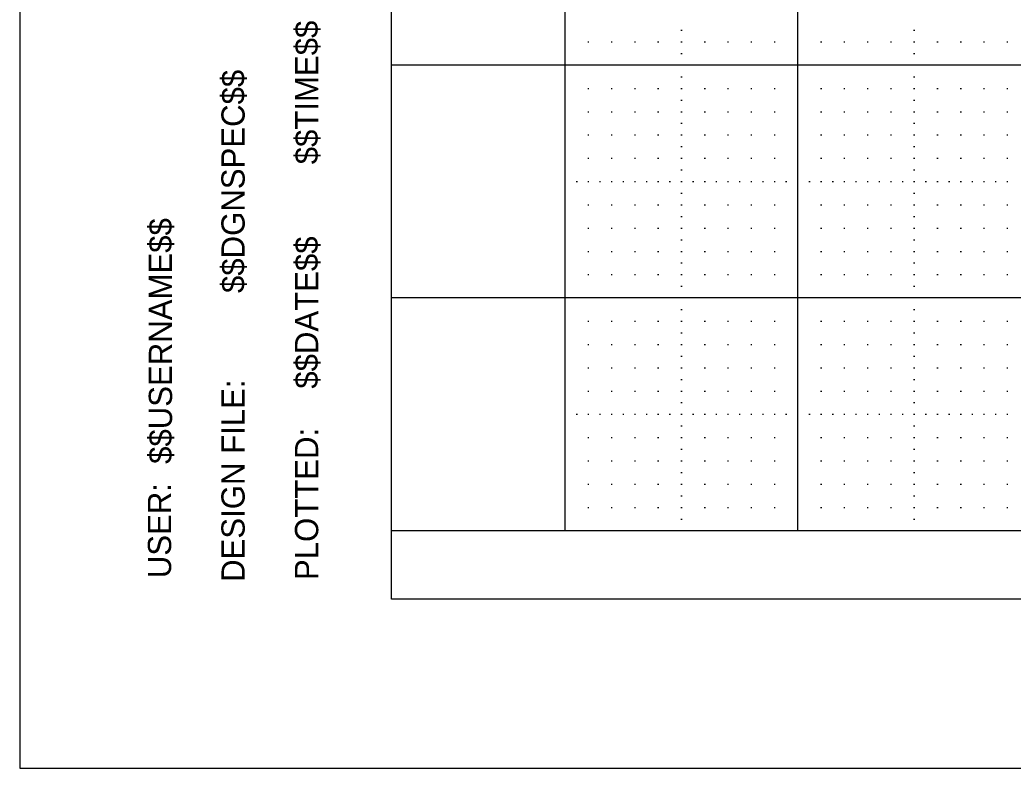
# Model space of a CAD drawing. Extents: x 0 to 34.3, y 0 to 22.
# Drawn here: x 0 to 4.268, y 0 to 3.214 of the extents above; entities that cross this region are included whole.
import ezdxf

# ---------------------------------------------------------------- set-up
doc = ezdxf.new("R2010")
doc.units = 0
for name, color, linetype in [('Level 1', 7, 'Continuous'), ('Level 4', 7, 'Continuous'), ('Level 5', 7, 'Continuous'), ('Level 63', 7, 'Continuous'), ('R_Border_Dark', 7, 'Continuous')]:
    doc.layers.add(name, color=color, linetype=linetype)

msp = doc.modelspace()

# ---------------------------------------------------------------- linework, layer by layer
at = {"layer": 'Level 1'}
for p, q in [((1.597, 0.726), (1.597, 21.272)), ((33.215, 0.726), (1.597, 0.726))]:
    msp.add_line(p, q, dxfattribs=at)
msp.add_lwpolyline([(2.343, 9.02), (32.343, 9.02), (32.343, 1.02), (2.343, 1.02)], close=True, dxfattribs=at)
at = {"layer": 'Level 4'}
msp.add_line((33.215, 1.02), (1.597, 1.02), dxfattribs=at)
at = {"layer": 'Level 5'}
for p, q in [((2.8405, 3.17), (2.8455, 3.17)), ((3.8405, 3.17), (3.8455, 3.17)), ((2.4405, 3.12), (2.4455, 3.12)), ((2.5405, 3.12), (2.5455, 3.12)), ((2.6405, 3.12), (2.6455, 3.12)), ((2.7405, 3.12), (2.7455, 3.12)), ((2.8405, 3.12), (2.8455, 3.12)), ((2.9405, 3.12), (2.9455, 3.12)), ((3.0405, 3.12), (3.0455, 3.12)), ((3.1405, 3.12), (3.1455, 3.12)), ((3.2405, 3.12), (3.2455, 3.12)), ((3.4405, 3.12), (3.4455, 3.12)), ((3.5405, 3.12), (3.5455, 3.12)), ((3.6405, 3.12), (3.6455, 3.12)), ((3.7405, 3.12), (3.7455, 3.12)), ((3.8405, 3.12), (3.8455, 3.12)), ((3.9405, 3.12), (3.9455, 3.12)), ((4.0405, 3.12), (4.0455, 3.12)), ((4.1405, 3.12), (4.1455, 3.12)), ((4.2405, 3.12), (4.2455, 3.12)), ((2.8405, 3.07), (2.8455, 3.07)), ((3.8405, 3.07), (3.8455, 3.07)), ((2.8405, 2.97), (2.8455, 2.97)), ((3.8405, 2.97), (3.8455, 2.97)), ((2.4405, 2.92), (2.4455, 2.92)), ((2.5405, 2.92), (2.5455, 2.92)), ((2.6405, 2.92), (2.6455, 2.92)), ((2.7405, 2.92), (2.7455, 2.92)), ((2.8405, 2.92), (2.8455, 2.92)), ((2.9405, 2.92), (2.9455, 2.92)), ((3.0405, 2.92), (3.0455, 2.92)), ((3.1405, 2.92), (3.1455, 2.92)), ((3.2405, 2.92), (3.2455, 2.92)), ((3.4405, 2.92), (3.4455, 2.92)), ((3.5405, 2.92), (3.5455, 2.92)), ((3.6405, 2.92), (3.6455, 2.92)), ((3.7405, 2.92), (3.7455, 2.92)), ((3.8405, 2.92), (3.8455, 2.92)), ((3.9405, 2.92), (3.9455, 2.92)), ((4.0405, 2.92), (4.0455, 2.92)), ((4.1405, 2.92), (4.1455, 2.92)), ((4.2405, 2.92), (4.2455, 2.92)), ((2.8405, 2.87), (2.8455, 2.87)), ((3.8405, 2.87), (3.8455, 2.87)), ((2.4405, 2.82), (2.4455, 2.82)), ((2.5405, 2.82), (2.5455, 2.82)), ((2.6405, 2.82), (2.6455, 2.82)), ((2.7405, 2.82), (2.7455, 2.82)), ((2.8405, 2.82), (2.8455, 2.82)), ((2.9405, 2.82), (2.9455, 2.82)), ((3.0405, 2.82), (3.0455, 2.82)), ((3.1405, 2.82), (3.1455, 2.82)), ((3.2405, 2.82), (3.2455, 2.82)), ((3.4405, 2.82), (3.4455, 2.82)), ((3.5405, 2.82), (3.5455, 2.82)), ((3.6405, 2.82), (3.6455, 2.82)), ((3.7405, 2.82), (3.7455, 2.82)), ((3.8405, 2.82), (3.8455, 2.82)), ((3.9405, 2.82), (3.9455, 2.82)), ((4.0405, 2.82), (4.0455, 2.82)), ((4.1405, 2.82), (4.1455, 2.82)), ((4.2405, 2.82), (4.2455, 2.82)), ((2.8405, 2.77), (2.8455, 2.77)), ((3.8405, 2.77), (3.8455, 2.77)), ((2.4405, 2.72), (2.4455, 2.72)), ((2.5405, 2.72), (2.5455, 2.72)), ((2.6405, 2.72), (2.6455, 2.72)), ((2.7405, 2.72), (2.7455, 2.72)), ((2.8405, 2.72), (2.8455, 2.72)), ((2.9405, 2.72), (2.9455, 2.72)), ((3.0405, 2.72), (3.0455, 2.72)), ((3.1405, 2.72), (3.1455, 2.72)), ((3.2405, 2.72), (3.2455, 2.72)), ((3.4405, 2.72), (3.4455, 2.72)), ((3.5405, 2.72), (3.5455, 2.72)), ((3.6405, 2.72), (3.6455, 2.72)), ((3.7405, 2.72), (3.7455, 2.72)), ((3.8405, 2.72), (3.8455, 2.72)), ((3.9405, 2.72), (3.9455, 2.72)), ((4.0405, 2.72), (4.0455, 2.72)), ((4.1405, 2.72), (4.1455, 2.72)), ((4.2405, 2.72), (4.2455, 2.72)), ((2.8405, 2.67), (2.8455, 2.67)), ((3.8405, 2.67), (3.8455, 2.67)), ((2.4405, 2.62), (2.4455, 2.62)), ((2.5405, 2.62), (2.5455, 2.62)), ((2.6405, 2.62), (2.6455, 2.62)), ((2.7405, 2.62), (2.7455, 2.62)), ((2.8405, 2.62), (2.8455, 2.62)), ((2.9405, 2.62), (2.9455, 2.62)), ((3.0405, 2.62), (3.0455, 2.62)), ((3.1405, 2.62), (3.1455, 2.62)), ((3.2405, 2.62), (3.2455, 2.62)), ((3.4405, 2.62), (3.4455, 2.62)), ((3.5405, 2.62), (3.5455, 2.62)), ((3.6405, 2.62), (3.6455, 2.62)), ((3.7405, 2.62), (3.7455, 2.62)), ((3.8405, 2.62), (3.8455, 2.62)), ((3.9405, 2.62), (3.9455, 2.62)), ((4.0405, 2.62), (4.0455, 2.62)), ((4.1405, 2.62), (4.1455, 2.62)), ((4.2405, 2.62), (4.2455, 2.62)), ((2.8405, 2.57), (2.8455, 2.57)), ((3.8405, 2.57), (3.8455, 2.57)), ((2.3905, 2.52), (2.3955, 2.52)), ((2.4405, 2.52), (2.4455, 2.52)), ((2.4905, 2.52), (2.4955, 2.52)), ((2.5405, 2.52), (2.5455, 2.52)), ((2.5905, 2.52), (2.5955, 2.52)), ((2.6405, 2.52), (2.6455, 2.52)), ((2.6905, 2.52), (2.6955, 2.52)), ((2.7405, 2.52), (2.7455, 2.52)), ((2.7905, 2.52), (2.7955, 2.52)), ((2.8405, 2.52), (2.8455, 2.52)), ((2.8905, 2.52), (2.8955, 2.52)), ((2.9405, 2.52), (2.9455, 2.52)), ((2.9905, 2.52), (2.9955, 2.52)), ((3.0405, 2.52), (3.0455, 2.52)), ((3.0905, 2.52), (3.0955, 2.52)), ((3.1405, 2.52), (3.1455, 2.52)), ((3.1905, 2.52), (3.1955, 2.52)), ((3.2405, 2.52), (3.2455, 2.52)), ((3.2905, 2.52), (3.2955, 2.52)), ((3.3905, 2.52), (3.3955, 2.52)), ((3.4405, 2.52), (3.4455, 2.52)), ((3.4905, 2.52), (3.4955, 2.52)), ((3.5405, 2.52), (3.5455, 2.52)), ((3.5905, 2.52), (3.5955, 2.52)), ((3.6405, 2.52), (3.6455, 2.52)), ((3.6905, 2.52), (3.6955, 2.52)), ((3.7405, 2.52), (3.7455, 2.52)), ((3.7905, 2.52), (3.7955, 2.52)), ((3.8405, 2.52), (3.8455, 2.52)), ((3.8905, 2.52), (3.8955, 2.52)), ((3.9405, 2.52), (3.9455, 2.52)), ((3.9905, 2.52), (3.9955, 2.52)), ((4.0405, 2.52), (4.0455, 2.52)), ((4.0905, 2.52), (4.0955, 2.52)), ((4.1405, 2.52), (4.1455, 2.52)), ((4.1905, 2.52), (4.1955, 2.52)), ((4.2405, 2.52), (4.2455, 2.52)), ((2.8405, 2.47), (2.8455, 2.47)), ((3.8405, 2.47), (3.8455, 2.47)), ((2.4405, 2.42), (2.4455, 2.42)), ((2.5405, 2.42), (2.5455, 2.42)), ((2.6405, 2.42), (2.6455, 2.42)), ((2.7405, 2.42), (2.7455, 2.42)), ((2.8405, 2.42), (2.8455, 2.42)), ((2.9405, 2.42), (2.9455, 2.42)), ((3.0405, 2.42), (3.0455, 2.42)), ((3.1405, 2.42), (3.1455, 2.42)), ((3.2405, 2.42), (3.2455, 2.42)), ((3.4405, 2.42), (3.4455, 2.42)), ((3.5405, 2.42), (3.5455, 2.42)), ((3.6405, 2.42), (3.6455, 2.42)), ((3.7405, 2.42), (3.7455, 2.42)), ((3.8405, 2.42), (3.8455, 2.42)), ((3.9405, 2.42), (3.9455, 2.42)), ((4.0405, 2.42), (4.0455, 2.42)), ((4.1405, 2.42), (4.1455, 2.42)), ((4.2405, 2.42), (4.2455, 2.42)), ((2.8405, 2.37), (2.8455, 2.37)), ((3.8405, 2.37), (3.8455, 2.37)), ((2.4405, 2.32), (2.4455, 2.32)), ((2.5405, 2.32), (2.5455, 2.32)), ((2.6405, 2.32), (2.6455, 2.32)), ((2.7405, 2.32), (2.7455, 2.32)), ((2.8405, 2.32), (2.8455, 2.32)), ((2.9405, 2.32), (2.9455, 2.32)), ((3.0405, 2.32), (3.0455, 2.32)), ((3.1405, 2.32), (3.1455, 2.32)), ((3.2405, 2.32), (3.2455, 2.32)), ((3.4405, 2.32), (3.4455, 2.32)), ((3.5405, 2.32), (3.5455, 2.32)), ((3.6405, 2.32), (3.6455, 2.32)), ((3.7405, 2.32), (3.7455, 2.32)), ((3.8405, 2.32), (3.8455, 2.32)), ((3.9405, 2.32), (3.9455, 2.32)), ((4.0405, 2.32), (4.0455, 2.32)), ((4.1405, 2.32), (4.1455, 2.32)), ((4.2405, 2.32), (4.2455, 2.32)), ((2.8405, 2.27), (2.8455, 2.27)), ((3.8405, 2.27), (3.8455, 2.27)), ((2.4405, 2.22), (2.4455, 2.22)), ((2.5405, 2.22), (2.5455, 2.22)), ((2.6405, 2.22), (2.6455, 2.22)), ((2.7405, 2.22), (2.7455, 2.22)), ((2.8405, 2.22), (2.8455, 2.22)), ((2.9405, 2.22), (2.9455, 2.22)), ((3.0405, 2.22), (3.0455, 2.22)), ((3.1405, 2.22), (3.1455, 2.22)), ((3.2405, 2.22), (3.2455, 2.22)), ((3.4405, 2.22), (3.4455, 2.22)), ((3.5405, 2.22), (3.5455, 2.22)), ((3.6405, 2.22), (3.6455, 2.22)), ((3.7405, 2.22), (3.7455, 2.22)), ((3.8405, 2.22), (3.8455, 2.22)), ((3.9405, 2.22), (3.9455, 2.22)), ((4.0405, 2.22), (4.0455, 2.22)), ((4.1405, 2.22), (4.1455, 2.22)), ((4.2405, 2.22), (4.2455, 2.22)), ((2.8405, 2.17), (2.8455, 2.17)), ((3.8405, 2.17), (3.8455, 2.17)), ((2.4405, 2.12), (2.4455, 2.12)), ((2.5405, 2.12), (2.5455, 2.12)), ((2.6405, 2.12), (2.6455, 2.12)), ((2.7405, 2.12), (2.7455, 2.12)), ((2.8405, 2.12), (2.8455, 2.12)), ((2.9405, 2.12), (2.9455, 2.12)), ((3.0405, 2.12), (3.0455, 2.12)), ((3.1405, 2.12), (3.1455, 2.12)), ((3.2405, 2.12), (3.2455, 2.12)), ((3.4405, 2.12), (3.4455, 2.12)), ((3.5405, 2.12), (3.5455, 2.12)), ((3.6405, 2.12), (3.6455, 2.12)), ((3.7405, 2.12), (3.7455, 2.12)), ((3.8405, 2.12), (3.8455, 2.12)), ((3.9405, 2.12), (3.9455, 2.12)), ((4.0405, 2.12), (4.0455, 2.12)), ((4.1405, 2.12), (4.1455, 2.12)), ((4.2405, 2.12), (4.2455, 2.12)), ((2.8405, 2.07), (2.8455, 2.07)), ((3.8405, 2.07), (3.8455, 2.07)), ((2.8405, 1.97), (2.8455, 1.97)), ((3.8405, 1.97), (3.8455, 1.97)), ((2.4405, 1.92), (2.4455, 1.92)), ((2.5405, 1.92), (2.5455, 1.92)), ((2.6405, 1.92), (2.6455, 1.92)), ((2.7405, 1.92), (2.7455, 1.92)), ((2.8405, 1.92), (2.8455, 1.92)), ((2.9405, 1.92), (2.9455, 1.92)), ((3.0405, 1.92), (3.0455, 1.92)), ((3.1405, 1.92), (3.1455, 1.92)), ((3.2405, 1.92), (3.2455, 1.92)), ((3.4405, 1.92), (3.4455, 1.92)), ((3.5405, 1.92), (3.5455, 1.92)), ((3.6405, 1.92), (3.6455, 1.92)), ((3.7405, 1.92), (3.7455, 1.92)), ((3.8405, 1.92), (3.8455, 1.92)), ((3.9405, 1.92), (3.9455, 1.92)), ((4.0405, 1.92), (4.0455, 1.92)), ((4.1405, 1.92), (4.1455, 1.92)), ((4.2405, 1.92), (4.2455, 1.92)), ((2.8405, 1.87), (2.8455, 1.87)), ((3.8405, 1.87), (3.8455, 1.87)), ((2.4405, 1.82), (2.4455, 1.82)), ((2.5405, 1.82), (2.5455, 1.82)), ((2.6405, 1.82), (2.6455, 1.82)), ((2.7405, 1.82), (2.7455, 1.82)), ((2.8405, 1.82), (2.8455, 1.82)), ((2.9405, 1.82), (2.9455, 1.82)), ((3.0405, 1.82), (3.0455, 1.82)), ((3.1405, 1.82), (3.1455, 1.82)), ((3.2405, 1.82), (3.2455, 1.82)), ((3.4405, 1.82), (3.4455, 1.82)), ((3.5405, 1.82), (3.5455, 1.82)), ((3.6405, 1.82), (3.6455, 1.82)), ((3.7405, 1.82), (3.7455, 1.82)), ((3.8405, 1.82), (3.8455, 1.82)), ((3.9405, 1.82), (3.9455, 1.82)), ((4.0405, 1.82), (4.0455, 1.82)), ((4.1405, 1.82), (4.1455, 1.82)), ((4.2405, 1.82), (4.2455, 1.82)), ((2.8405, 1.77), (2.8455, 1.77)), ((3.8405, 1.77), (3.8455, 1.77)), ((2.4405, 1.72), (2.4455, 1.72)), ((2.5405, 1.72), (2.5455, 1.72)), ((2.6405, 1.72), (2.6455, 1.72)), ((2.7405, 1.72), (2.7455, 1.72)), ((2.8405, 1.72), (2.8455, 1.72)), ((2.9405, 1.72), (2.9455, 1.72)), ((3.0405, 1.72), (3.0455, 1.72)), ((3.1405, 1.72), (3.1455, 1.72)), ((3.2405, 1.72), (3.2455, 1.72)), ((3.4405, 1.72), (3.4455, 1.72)), ((3.5405, 1.72), (3.5455, 1.72)), ((3.6405, 1.72), (3.6455, 1.72)), ((3.7405, 1.72), (3.7455, 1.72)), ((3.8405, 1.72), (3.8455, 1.72)), ((3.9405, 1.72), (3.9455, 1.72)), ((4.0405, 1.72), (4.0455, 1.72)), ((4.1405, 1.72), (4.1455, 1.72)), ((4.2405, 1.72), (4.2455, 1.72)), ((2.8405, 1.67), (2.8455, 1.67)), ((3.8405, 1.67), (3.8455, 1.67)), ((2.4405, 1.62), (2.4455, 1.62)), ((2.5405, 1.62), (2.5455, 1.62)), ((2.6405, 1.62), (2.6455, 1.62)), ((2.7405, 1.62), (2.7455, 1.62)), ((2.8405, 1.62), (2.8455, 1.62)), ((2.9405, 1.62), (2.9455, 1.62)), ((3.0405, 1.62), (3.0455, 1.62)), ((3.1405, 1.62), (3.1455, 1.62)), ((3.2405, 1.62), (3.2455, 1.62)), ((3.4405, 1.62), (3.4455, 1.62)), ((3.5405, 1.62), (3.5455, 1.62)), ((3.6405, 1.62), (3.6455, 1.62)), ((3.7405, 1.62), (3.7455, 1.62)), ((3.8405, 1.62), (3.8455, 1.62)), ((3.9405, 1.62), (3.9455, 1.62)), ((4.0405, 1.62), (4.0455, 1.62)), ((4.1405, 1.62), (4.1455, 1.62)), ((4.2405, 1.62), (4.2455, 1.62)), ((2.8405, 1.57), (2.8455, 1.57)), ((3.8405, 1.57), (3.8455, 1.57)), ((2.3905, 1.52), (2.3955, 1.52)), ((2.4405, 1.52), (2.4455, 1.52)), ((2.4905, 1.52), (2.4955, 1.52)), ((2.5405, 1.52), (2.5455, 1.52)), ((2.5905, 1.52), (2.5955, 1.52)), ((2.6405, 1.52), (2.6455, 1.52)), ((2.6905, 1.52), (2.6955, 1.52)), ((2.7405, 1.52), (2.7455, 1.52)), ((2.7905, 1.52), (2.7955, 1.52)), ((2.8405, 1.52), (2.8455, 1.52)), ((2.8905, 1.52), (2.8955, 1.52)), ((2.9405, 1.52), (2.9455, 1.52)), ((2.9905, 1.52), (2.9955, 1.52)), ((3.0405, 1.52), (3.0455, 1.52)), ((3.0905, 1.52), (3.0955, 1.52)), ((3.1405, 1.52), (3.1455, 1.52)), ((3.1905, 1.52), (3.1955, 1.52)), ((3.2405, 1.52), (3.2455, 1.52)), ((3.2905, 1.52), (3.2955, 1.52)), ((3.3905, 1.52), (3.3955, 1.52)), ((3.4405, 1.52), (3.4455, 1.52)), ((3.4905, 1.52), (3.4955, 1.52)), ((3.5405, 1.52), (3.5455, 1.52)), ((3.5905, 1.52), (3.5955, 1.52)), ((3.6405, 1.52), (3.6455, 1.52)), ((3.6905, 1.52), (3.6955, 1.52)), ((3.7405, 1.52), (3.7455, 1.52)), ((3.7905, 1.52), (3.7955, 1.52)), ((3.8405, 1.52), (3.8455, 1.52)), ((3.8905, 1.52), (3.8955, 1.52)), ((3.9405, 1.52), (3.9455, 1.52)), ((3.9905, 1.52), (3.9955, 1.52)), ((4.0405, 1.52), (4.0455, 1.52)), ((4.0905, 1.52), (4.0955, 1.52)), ((4.1405, 1.52), (4.1455, 1.52)), ((4.1905, 1.52), (4.1955, 1.52)), ((4.2405, 1.52), (4.2455, 1.52)), ((2.8405, 1.47), (2.8455, 1.47)), ((3.8405, 1.47), (3.8455, 1.47)), ((2.4405, 1.42), (2.4455, 1.42)), ((2.5405, 1.42), (2.5455, 1.42)), ((2.6405, 1.42), (2.6455, 1.42)), ((2.7405, 1.42), (2.7455, 1.42)), ((2.8405, 1.42), (2.8455, 1.42)), ((2.9405, 1.42), (2.9455, 1.42)), ((3.0405, 1.42), (3.0455, 1.42)), ((3.1405, 1.42), (3.1455, 1.42)), ((3.2405, 1.42), (3.2455, 1.42)), ((3.4405, 1.42), (3.4455, 1.42)), ((3.5405, 1.42), (3.5455, 1.42)), ((3.6405, 1.42), (3.6455, 1.42)), ((3.7405, 1.42), (3.7455, 1.42)), ((3.8405, 1.42), (3.8455, 1.42)), ((3.9405, 1.42), (3.9455, 1.42)), ((4.0405, 1.42), (4.0455, 1.42)), ((4.1405, 1.42), (4.1455, 1.42)), ((4.2405, 1.42), (4.2455, 1.42)), ((2.8405, 1.37), (2.8455, 1.37)), ((3.8405, 1.37), (3.8455, 1.37)), ((2.4405, 1.32), (2.4455, 1.32)), ((2.5405, 1.32), (2.5455, 1.32)), ((2.6405, 1.32), (2.6455, 1.32)), ((2.7405, 1.32), (2.7455, 1.32)), ((2.8405, 1.32), (2.8455, 1.32)), ((2.9405, 1.32), (2.9455, 1.32)), ((3.0405, 1.32), (3.0455, 1.32)), ((3.1405, 1.32), (3.1455, 1.32)), ((3.2405, 1.32), (3.2455, 1.32)), ((3.4405, 1.32), (3.4455, 1.32)), ((3.5405, 1.32), (3.5455, 1.32)), ((3.6405, 1.32), (3.6455, 1.32)), ((3.7405, 1.32), (3.7455, 1.32)), ((3.8405, 1.32), (3.8455, 1.32)), ((3.9405, 1.32), (3.9455, 1.32)), ((4.0405, 1.32), (4.0455, 1.32)), ((4.1405, 1.32), (4.1455, 1.32)), ((4.2405, 1.32), (4.2455, 1.32)), ((2.8405, 1.27), (2.8455, 1.27)), ((3.8405, 1.27), (3.8455, 1.27)), ((2.4405, 1.22), (2.4455, 1.22)), ((2.5405, 1.22), (2.5455, 1.22)), ((2.6405, 1.22), (2.6455, 1.22)), ((2.7405, 1.22), (2.7455, 1.22)), ((2.8405, 1.22), (2.8455, 1.22)), ((2.9405, 1.22), (2.9455, 1.22)), ((3.0405, 1.22), (3.0455, 1.22)), ((3.1405, 1.22), (3.1455, 1.22)), ((3.2405, 1.22), (3.2455, 1.22)), ((3.4405, 1.22), (3.4455, 1.22)), ((3.5405, 1.22), (3.5455, 1.22)), ((3.6405, 1.22), (3.6455, 1.22)), ((3.7405, 1.22), (3.7455, 1.22)), ((3.8405, 1.22), (3.8455, 1.22)), ((3.9405, 1.22), (3.9455, 1.22)), ((4.0405, 1.22), (4.0455, 1.22)), ((4.1405, 1.22), (4.1455, 1.22)), ((4.2405, 1.22), (4.2455, 1.22)), ((2.8405, 1.17), (2.8455, 1.17)), ((3.8405, 1.17), (3.8455, 1.17)), ((2.4405, 1.12), (2.4455, 1.12)), ((2.5405, 1.12), (2.5455, 1.12)), ((2.6405, 1.12), (2.6455, 1.12)), ((2.7405, 1.12), (2.7455, 1.12)), ((2.8405, 1.12), (2.8455, 1.12)), ((2.9405, 1.12), (2.9455, 1.12)), ((3.0405, 1.12), (3.0455, 1.12)), ((3.1405, 1.12), (3.1455, 1.12)), ((3.2405, 1.12), (3.2455, 1.12)), ((3.4405, 1.12), (3.4455, 1.12)), ((3.5405, 1.12), (3.5455, 1.12)), ((3.6405, 1.12), (3.6455, 1.12)), ((3.7405, 1.12), (3.7455, 1.12)), ((3.8405, 1.12), (3.8455, 1.12)), ((3.9405, 1.12), (3.9455, 1.12)), ((4.0405, 1.12), (4.0455, 1.12)), ((4.1405, 1.12), (4.1455, 1.12)), ((4.2405, 1.12), (4.2455, 1.12)), ((2.8405, 1.07), (2.8455, 1.07)), ((3.8405, 1.07), (3.8455, 1.07))]:
    msp.add_line(p, q, dxfattribs=at)
at = {"layer": 'Level 63'}
msp.add_lwpolyline([(0, 0), (34, 0), (34, 22), (0, 22)], close=True, dxfattribs=at)
msp.add_lwpolyline([(32.343, 9.02), (32.343, 1.02), (2.343, 1.02), (2.343, 9.02)], dxfattribs=at)
at = {"layer": 'R_Border_Dark'}
for p, q in [((2.343, 1.02), (2.343, 9.02)), ((3.343, 1.02), (3.343, 9.02)), ((33.215, 3.02), (1.597, 3.02)), ((33.215, 2.02), (1.597, 2.02))]:
    msp.add_line(p, q, dxfattribs=at)
msp.add_lwpolyline([(32.343, 9.02), (32.343, 1.02), (2.343, 1.02), (2.343, 9.02)], dxfattribs=at)

# ---------------------------------------------------------------- texts
at = {"layer": 'Level 1'}
for s, height, p in [('$$TIME$$', 0.1, (1.282, 2.594)), ('$$DGNSPEC$$', 0.100002, (0.966, 2.041)), ('$$USERNAME$$', 0.100002, (0.654, 1.307)), ('$$DATE$$', 0.1, (1.282, 1.63)), ('DESIGN FILE:', 0.100002, (0.966, 0.8)), ('PLOTTED:', 0.1, (1.282, 0.808)), ('USER:', 0.1, (0.65, 0.816))]:
    msp.add_text(s, height=height, rotation=90, dxfattribs=at).set_placement(p)

doc.saveas('drawing.dxf')
